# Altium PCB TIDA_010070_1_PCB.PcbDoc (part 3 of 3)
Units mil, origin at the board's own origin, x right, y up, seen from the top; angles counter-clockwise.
Board outline 3224 x 3643 mil, 4 copper layers (Top Layer, Ground, Power, Bottom Layer), stack 90.4 mil thick; 156 components, 57 nets, 333 pads, 411 vias.
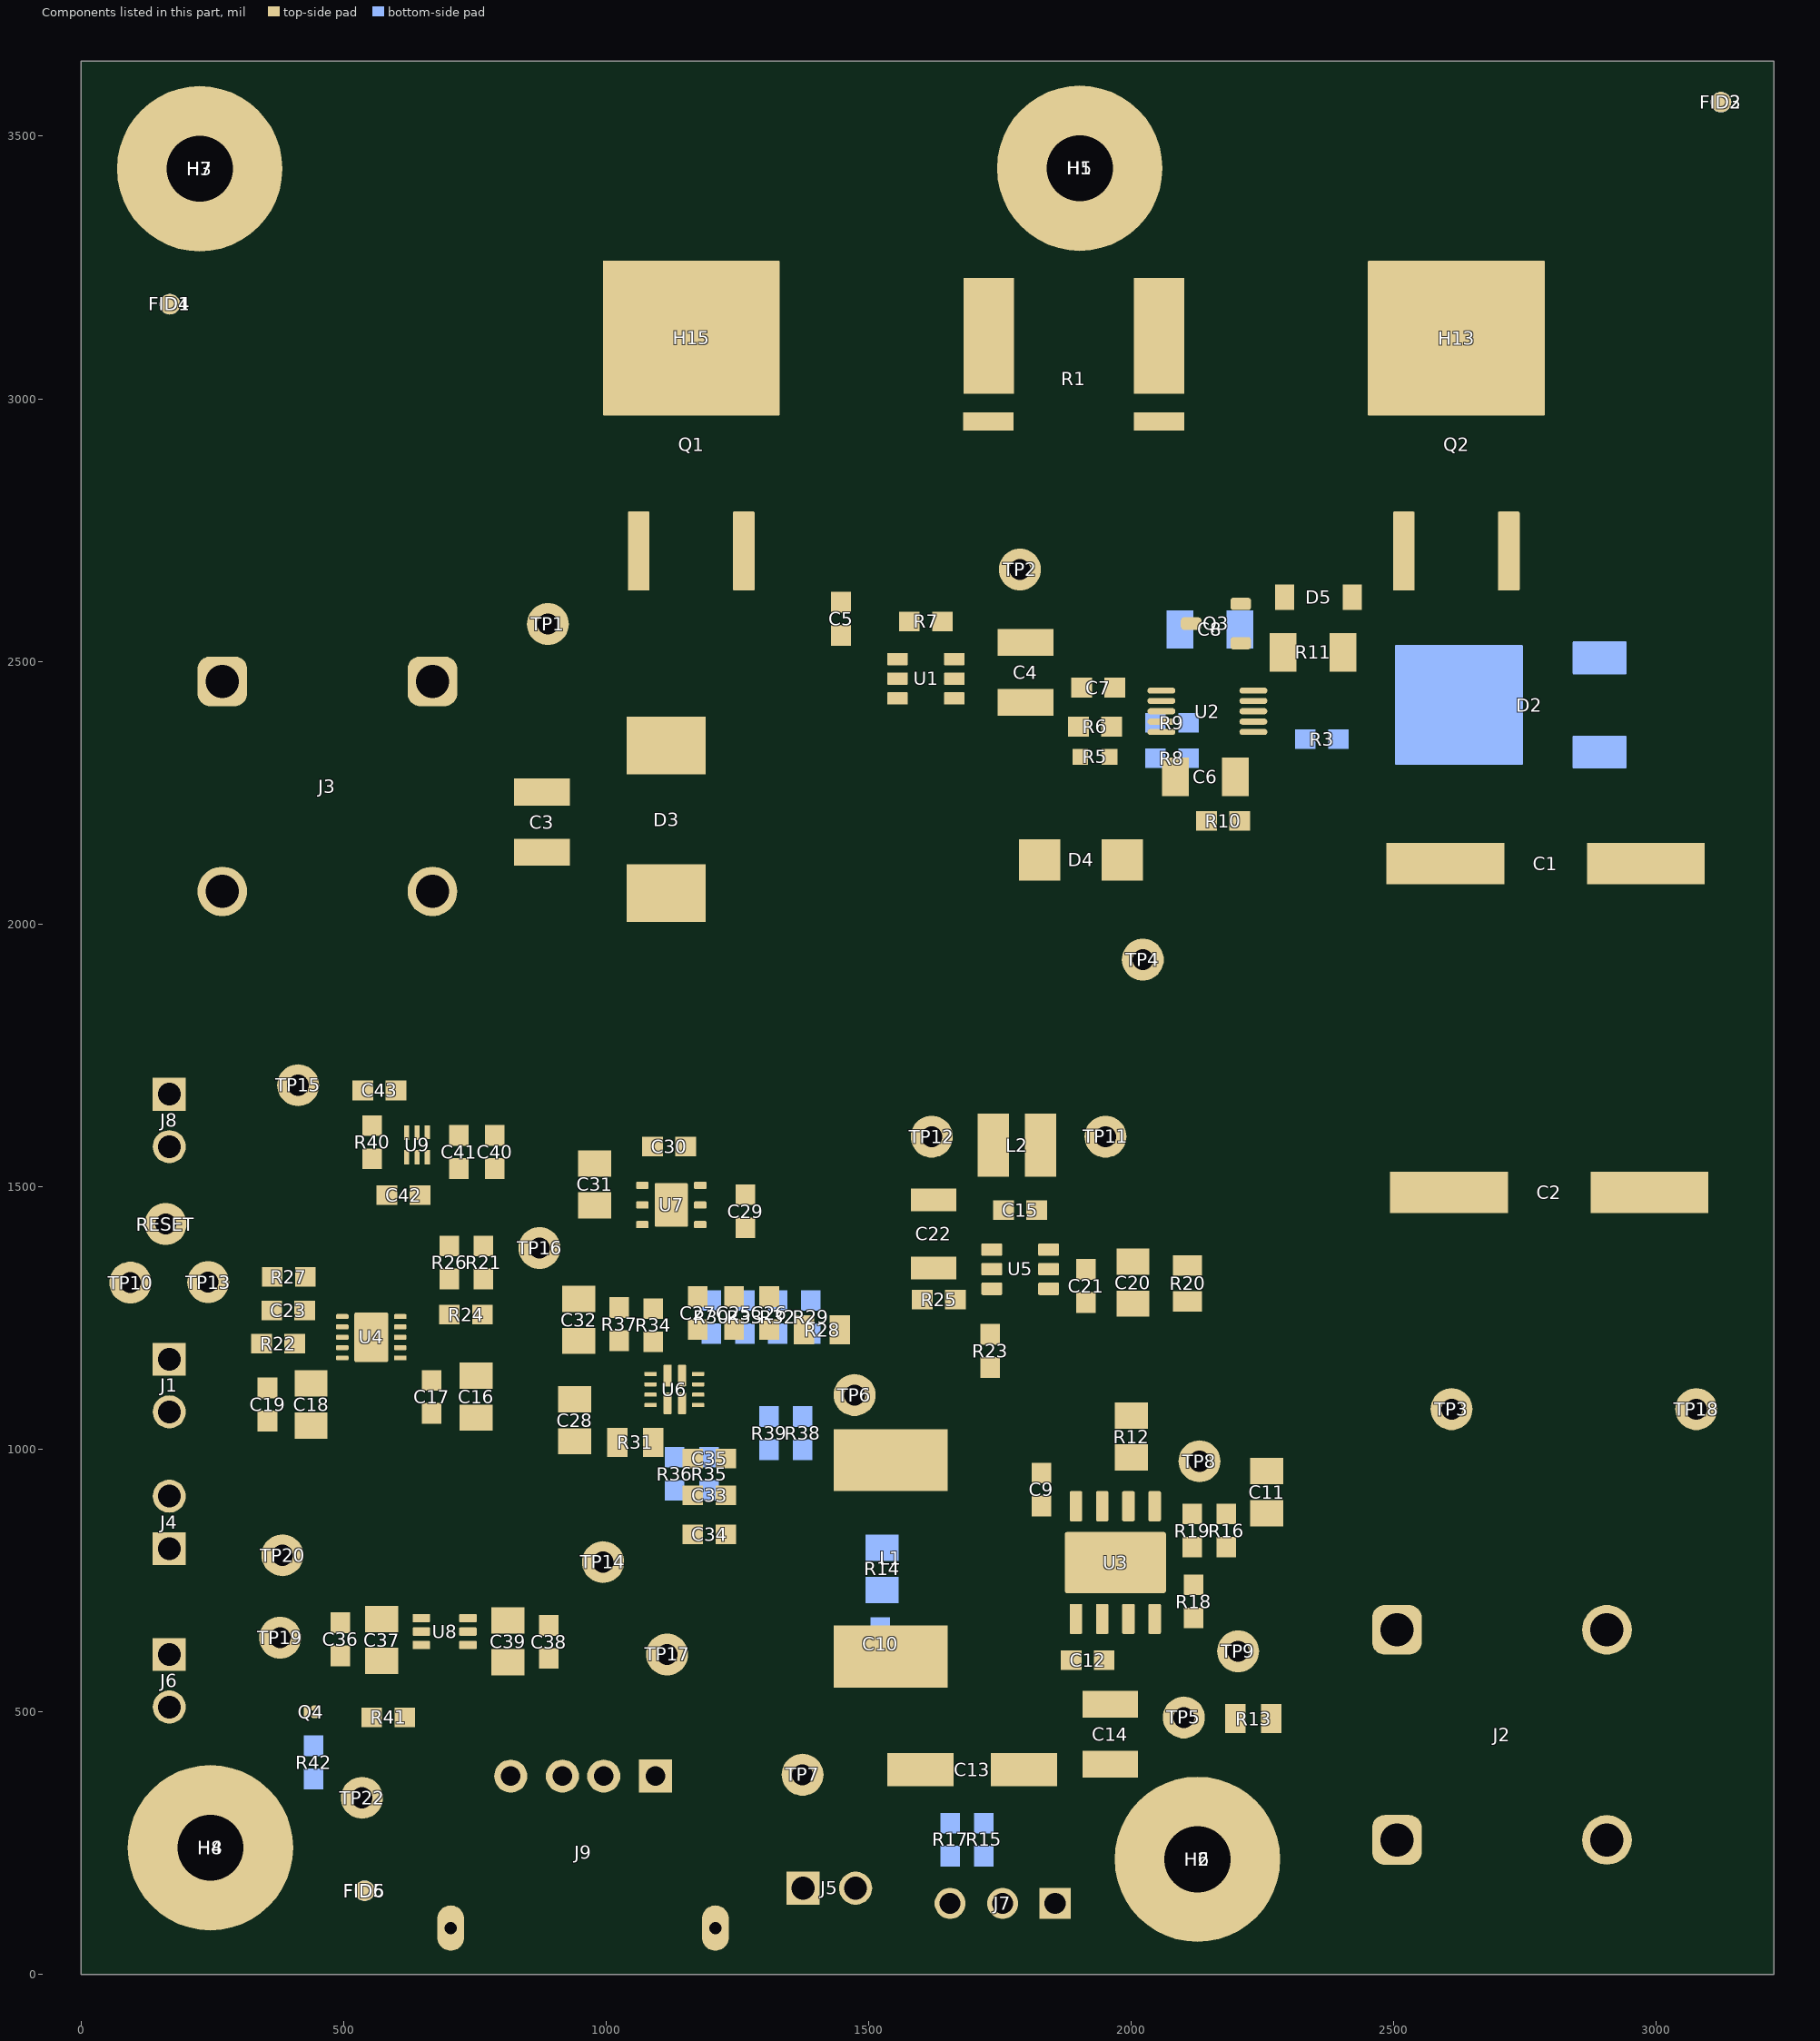
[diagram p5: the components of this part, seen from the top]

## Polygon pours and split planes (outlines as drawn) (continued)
NetC4_2 on Top Layer "Top Layer-No Net" (solid, remove dead copper, pour order 94): 1866,2496 1870,2500 1930,2500 1940,2510 1940,2741 1881,2800 1754,2800 1660,2894 1660,2990 1670,3000 1770,3000 1780,3010 1780,3229.15 1769.15,3240 1736.15,3240 1671,3305.15 1671,3582 1643,3610 419,3610 400,3591 400,3355.35 304.65,3260 304.65,3143.65 271,3110 60,3110 36.3,3086.3 36.3,2723.7 50,2710 470,2710 970,2710 980,2720 980,2807 989,2816 1437,2816 1442,2811 1442,2679 1451,2670 1595,2670 1621,2644 1621,2510 1635,2496 1697,2496
NetC5_1 on Top Layer "Top Layer-No Net" (solid, remove dead copper, pour order 92): 1594,2635.06 1583.06,2646 1409.02,2646 1404,2640.98 1404,2596 1409,2591 1529,2591 1539,2581 1539,2501 1549,2491 1573.92,2491 1573.92,2535.92 1589,2551 1594,2556
GND on Top Layer "Top Layer-No Net" (solid, remove dead copper, pour order 162): 623,1522 625,1524 633,1524 636,1527 644,1527 647,1524 680,1524 687,1531 687,1556 689,1558 807,1558 809,1556 809,1455 807,1453 625,1453 623,1455
Reset on Top Layer "Top Layer-No Net" (solid, remove dead copper, pour order 164): 565,1466 339,1466 258,1385 130,1385 120,1395 120,1461 130,1471 254,1471 352,1569 625,1569 625,1542 602,1519 602,1503
VCC_5V_MAINS on Top Layer "Top Layer-No Net" (solid, remove dead copper, pour order 166): 715.01,1178 761.11,1224.1 782.9,1224.1 790,1217 790,1116.36 784.64,1111 618,1111 600.49,1128.51 600.49,1178
VCC_ENC1 on Top Layer "Top Layer-No Net" (solid, remove dead copper, pour order 168): 50,1120 40,1130 40,1340 60,1360 119,1360 140,1339 140,1231 150,1221 334,1221 363.25,1221 367.54,1216.7 367.54,1168.51 374.71,1161 473.72,1161 486.35,1173.63 501.91,1173.63 504.26,1171.28 504.26,1105.26 490,1091 326,1091 297,1120
GND on Top Layer "Top Layer-GND 1" (solid, remove dead copper, pour order 170): 341,1068 466.08,1068 480.05,1054.04 480.05,1028.95 488,1021 634,1021 644,1031 644,1079 650,1085 784.18,1085 804,1065.18 804,931 794,921 363.82,921 354,930.82 354,1001 334,1021 334,1061
NetC23_2 on Top Layer "Top Layer-GND" (solid, remove dead copper, pour order 172): 512,1349 512,1271.91 522,1261.91 522,1087.05 506,1071.05 506,1050 509,1047 615,1047 619,1051 619,1074.15 587,1106.15 587,1243 591.06,1247.06 634.06,1247.06 644,1257 644,1351 654,1361 720,1361 724,1365 724,1421 714,1431 365,1431 335,1401 335,1318 335,1252 341,1246 389,1246 392,1249 392,1356 396,1360 501,1360
V_5VBAT on Top Layer "Top Layer-GND" (solid, remove dead copper, pour order 176): 50,710 661,710 664,707 664,701.33 664,671 615,671 606,662 606,652 605,651 460,651 440,631 440,570 430,560 260,560 50,560 40,570 40,700
VCC_ENC2 on Top Layer "Top Layer-GND" (solid, remove dead copper, pour order 178): 714,654.59 721,647.59 766.1,647.59 772.69,641 924,641 934,651 934,832.45 906.45,860 100,860 50,860 40,850 40,750 50,740 705,740 714,731
GND on Top Layer "Top Layer-GND" (solid, remove dead copper, pour order 180): 599.82,626 614,611.82 614,581.33 630.33,565 667,565 684,582 684,621 694,631 914,631 924,621 924,542 912,530 670,530 660,520 660,431 649,420 605,420 594,431 594,541 590,545 487,545 469.26,562.74 469.26,620.26 475,626
GND on Top Layer "Top Layer-GND" (solid, remove dead copper, pour order 192): 2820,50 2836,34 3183,34 3189.7,40.7 3189.7,2620.3 3159.85,2650.15 2830.15,2650.15 2820,2640
VCC_48V on Top Layer "Top Layer-GND" (solid, remove dead copper, pour order 198): 2620,2770 2630,2780 2764,2780 2774,2770 2774,50 2759.3,35.3 2344.7,35.3 2330,50 2330,406 2306,430 2251,430 2240,441 2240,528 2252,540 2295.75,540 2330,574.25 2330,1121 2330,2207 2470,2347 2470,2396 2456,2410 2432,2410 2426,2416 2426,2432.51 2433.49,2440 2457,2440 2470,2453 2470,2560 2480,2570 2578,2570 2620,2612
GND on Bottom Layer "Top Layer-GND" (solid, remove dead copper, pour order 274): 2120.69,2171.31 2082,2210 2082,2303 2092,2313 2092,2502 2052,2542 2052,2638 2064,2650 2291,2650 3160,2650 3189.89,2620.11 3190,2614 3190,80 3140,30 80,30 40.12,69.88 40.12,2131.12 80,2171 1289.17,2171 1350.17,2110 1850,2110 1900,2060 1900,1863.95 1919.95,1844 2101,1844 2120.69,1863.69
VCC_5V_MAINS on Bottom Layer "Top Layer-GND" (solid, remove dead copper, pour order 200): 1649,1389.8 1649.2,1389.8 1660,1379 1675,1379 1690,1394 1690,1400 1690,1661 1680.15,1670.85 1400.46,1670.85 1390,1660.39 1390,1400 1400.2,1389.8 1479.82,1389.8 1529.74,1389.8
VCC_5V_USB on Bottom Layer "Top Layer-GND" (solid, remove dead copper, pour order 210): 1050,680 1171,680 1180,671 1180,340 1170,330 1049.2,330 1040,339.2 1040,670
VCC_48V on Bottom Layer "Top Layer-GND" (solid, remove dead copper, pour order 242): 2330,50 2344.7,35.3 2759.3,35.3 2770,46 2770,2760 2750,2780 2630,2780 2620,2770 2620,2612 2598,2590 2380,2590 2367,2577 2367,2244 2330,2207 2330,1119
NetC9_1 on Bottom Layer "Top Layer-GND" (solid, remove dead copper, pour order 244): 1470,800 1480,790 1570,790 1580,800 1580,830 1590,840 1720,840 1730,850 1730,910 1720,920 1480,920 1470,910
VCC_15V on Bottom Layer "Top Layer-GND" (solid, remove dead copper, pour order 246): 1559.88,539.12 1570,529 1570,507 1560,497 1560,339.12 1549.88,329 1310.94,329 1299.94,340 1299.94,569.7 1310,579.75 1480.26,579.75 1488.26,588.26 1490,590 1490,610 1500,620 1549.88,620 1559.88,610
NetC4_2 on Bottom Layer "Top Layer-No Net" (solid, remove dead copper, pour order 256): 304.65,3260 304.65,3143.65 271,3110 60,3110 36.3,3086.3 36.3,2723.7 50,2710 470,2710 970,2710 980,2720 980,2810 990,2820 1359,2820 1440,2739 1509,2670 1620,2559 1683,2496 1699,2480 1868.16,2480 1894,2480 1901,2473 1920,2473 1927,2480 1941,2494 1941,2740 1780,2901 1780,3196.15 1736.15,3240 1671,3305.15 1671,3582 1643,3610 419,3610 400,3591 400,3355.35
NetH13_1 on Bottom Layer "Top Layer-No Net" (solid, remove dead copper, pour order 262): 3027,3619.7 3050,3596.7 3050,3500 3060,3490 3187.33,3490 3195,3482.33 3194.7,3446 3194.7,2695.7 3179,2680 2815,2680 2804,2691 2804,2791 2789,2806 2434,2806 2419,2791 2419,2701 2398,2680 2125,2680 2113.98,2691.02 2113.98,2876.02 1980.81,3009.19 1980.81,3329.81 2061,3410 2061,3570 2110.7,3619.7
NetC5_2 on Bottom Layer "Top Layer-GND" (solid, remove dead copper, pour order 266): 2120.69,2144.31 1995,2270 1942.6,2270 1935,2262.4 1935,2252 1927,2244 1890.27,2244 1880,2254.27 1880,2380 1870,2390 1631,2390 1530,2491 1431,2590 1350,2590 1340,2580 1340,2162.44 1361.44,2141 1867.41,2141 1916,2092.03 1916,1883.91 1929.94,1869.98 2097.98,1869.98 2120.69,1892.69
GND on Ground "Top Layer-GND" (solid, remove dead copper, pour order 268): 1295.95,2171 80,2171 40.12,2131.12 40.12,69.88 70,40 3150,40 3190,80 3190,2614 3189.89,2620.11 3160,2650 2280.16,2650 2250,2620.14 2250,2080 2240,2070 2160,2070 2150,2060 2150,2000 2140,1990 1910,1990 1900,2000 1900,2060 1850,2110 1356.95,2110
NetC5_2 on Ground "Top Layer-No Net" (solid, remove dead copper, pour order 122): 2150,2070 2160,2080 2160.69,2080 2233,2080 2244,2091 2244,2561 2235,2570 1980.09,2570 1970,2559.77 1970,2460 1960,2450 1601,2450 1590.18,2460.82 1590.18,2554.82 1575,2570 1370,2570 1360,2560 1360,2150 1370,2140 1871,2140 1916.05,2094.95 1916.05,1883.95 1930.02,1869.98 2129.44,1869.98 2150,1890.54
NetC23_2 on Ground "Top Layer-GND" (solid, remove dead copper, pour order 174): 334,1431 714,1431 724,1421 724,1051 714,1041 333.8,1041 324,1050.8 324,1421
NetC4_2 on Ground "Top Layer-No Net" (solid, remove dead copper, pour order 250): 1780,3010 1780,2901 1941,2740 1941,2494 1927,2480 1868.16,2480 1699,2480 1630,2480 1620,2490 1620,2645 1595,2670 1449,2670 1440,2679 1440,2806 1430,2816 989,2816 980,2807 980,2720 970,2710 470,2710 50,2710 36.3,2723.7 36.3,3246.3 50,3260 304.65,3260 400,3355.35 400,3591 419,3610 1643,3610 1671,3582 1671,3305.15 1736.15,3240 1780,3196.15
NetH13_1 on Ground "Top Layer-No Net" (solid, remove dead copper, pour order 258): 1980.81,3009.44 1990,3000.25 2114.02,2876.22 2114,2691 2125,2680 2410,2680 2420,2690 2420,2792 2434,2806 2789,2806 2804,2791 2804,2691 2815,2680 3179,2680 3189.7,2690.7 3189.7,3601.71 3183.71,3607.7 2098.7,3607.7 2061,3570 2061,3403 1980.81,3322.81
VCC_5V_MAINS on Power "Top Layer-GND" (solid, remove dead copper, pour order 196): 810,1050 820,1060 820,1560 830,1570 1370,1570 1400,1540 1400,1450 1410,1440 1730,1440 1740,1450 1740,1898 1730,1908 501,1908 490,1897 490,1060 500,1050
NetC3_2 on Power "Top Layer-No Net" (solid, remove dead copper, pour order 182): 1329.99,2790 1340,2779.99 1340,2387 1357,2370 1613,2370 1640,2397 1640,2441 1680,2441 1680,2230 1670,2220 140,2220 130,2230 130,2667 144,2681 894.05,2681 1192.56,2681 1220,2708.44 1220,2780 1230,2790
VCC_48V on Power "Top Layer-No Net" (solid, remove dead copper, pour order 188): 3180,30 3190,40 3190,2640 3180,2650 2790,2650 2780,2660 2780,2770 2770,2780 2630,2780 2620,2770 2620,2669 2581,2630 2270,2630 2260,2620 2260,2190 2260,1204 2350,1114 2350,50 2370,30
VCC_15V on Power "Top Layer-GND" (solid, remove dead copper, pour order 202): 1190,790 1200,800 1400,800 1410,810 1410,880 1410,1369.64 1420.36,1380 2190,1380 2200,1370 2200,420 2190,410 1940,410 1930,400 1930,70 1920,60 1200,60 1190,70
NetC28_2 on Power "Top Layer-GND" (solid, remove dead copper, pour order 204): 830,1020 840,1030 910,1030 920,1040 920,1480 930,1490 1340,1490 1350,1480 1350,880 1340,870 839.76,870 830,879.75
NetC4_2 on Power "Top Layer-No Net" (solid, remove dead copper, pour order 254): 1780,2880 1941,2719 1941,2494 1927,2480 1868.16,2480 1699,2480 1450,2480 1440,2490 1440,2810 1434,2816 989,2816 980,2807 980,2720 970,2710 470,2710 50,2710 36.3,2723.7 36.3,3246.3 50,3260 304.65,3260 400,3355.35 400,3591 419,3610 1643,3610 1671,3582 1671,3305.15 1736.15,3240 1780,3196.15
NetH13_1 on Power "Top Layer-No Net" (solid, remove dead copper, pour order 260): 1979.97,2700.02 2000,2680 2397.96,2680 2419,2701.04 2419,2791 2434,2806 2789,2806 2805,2790 2805,2690 2815,2680 3179,2680 3189.7,2690.7 3189.7,3601.71 3183.71,3607.7 2098.7,3607.7 2061,3570 2061,3403 1980,3322

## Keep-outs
Keep-Out Layer:
  lines w10: 1,0 1,3643 3225,3643 3225,0 1,0
  text ".Layer_Name" at 611,-2376.19 h60

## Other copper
Top Layer:
  rectangle net GND: 1770,1290 1810,1360
  text ".Layer_Name" at 611,-2376.19 h60
Ground:
  pour cut-out: 2139.98,1239 2139.98,1214 2123,1214 2123,1239
  text "GROUND" at 611,-2376.19 h60
Power:
  pour cut-out: 2976,264 2976,249 2965.81,249 2965.81,264
  text "POWER" at 627,-2377 h60
Bottom Layer:
  pour cut-out: 1125,857.39 1135.08,857.39 1135.47,857 1135.47,846 1125.04,846 1125,846.04
  text ".Layer_Name" at 611,-2376.19 h60

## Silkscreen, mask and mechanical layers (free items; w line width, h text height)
Top Overlay:
  lines w6: 56.99,1862 56.99,1849.01 47.74,1849.01 47.74,1836.02 83.96,1836.02 83.96,1849.01 74.71,1849.01 74.71,1862 ; 301.86,1007.02 323,985.88 323,982 323,958 323,925 334,914 427,914 ; 313,1238 313,1354 351,1392 351,1433 ; 397,1510 450,1510 467,1493 467,1435 467,1231.51 455.49,1220 445,1209.51 445,1180 ; 480.02,1284 480.02,1300 496.52,1300 ; 550,1140 630,1140 630,1240 ; 556.2,1862 556.2,1849.01 546.95,1849.01 546.95,1836.02 583.17,1836.02 583.17,1849.01 573.92,1849.01 573.92,1862 ; 759.46,2459.74 820,2459.74 ; 760.53,2029.47 760.53,2090.01 ; 789.99,2429.2 789.99,2489.74 ; 1523.98,470 1553.98,470 ; 1538.98,455 1538.98,485 ; 1965,2222 1980,2237 1980,2284 ; 2160.28,768 2200,768 2213.25,754.75 2222.45,754.75 ; 2226,830 2288,830 2295,823 ; 2478.47,768.27 2539.01,768.27 ; 2509,737.73 2509,798.27 ; 2876.47,771.3 2937.01,771.3 ; 3106,43.99 3118.99,43.99 3118.99,34.74 3131.98,34.74 3131.98,70.96 3118.99,70.96 3118.99,62.01 3106.3,62.01 3106,61.71 ; 3106,543.2 3118.99,543.2 3118.99,533.95 3131.98,533.95 3131.98,570.17 3118.99,570.17 3118.99,560.92 3106,560.92 ; 427,914 420,921 420,907 427,914 ; 36.25,1862 731.99,1862 731.99,2662 36.25,2662 36.25,1862 ; 410,470 462,470 462,529 410,529 410,470 ; 2306,37.87 3106,37.87 3106,718.99 2306,718.99 2306,37.87
  text ".Layer_Name" at 611,-2376.19 h60
Bottom Overlay:
  lines w6: 2490,2280 2490,2562 2940,2562 2960,2562 2960,2280 2490,2280
  text ".Layer_Name" at 611,-2376.19 h60
Top Paste:
  text ".Layer_Name" at 611,-2376.19 h60
Bottom Paste:
  text ".Layer_Name" at 611,-2376.19 h60
Top Solder:
  region: 2250,2714 2243,2721 2243,3577 2258,3592 2993,3592 3007,3578 3007,2732 2989,2714 2835,2714 2835,2810 2830,2815 2408,2815 2399,2806 2399,2714
  region: 776,3571 1520,3571 1563,3528 1563,2726 1551,2714 1373.66,2714 1372.04,2715.62 1372.04,2815.62 951.62,2815.62 946,2810 946,2725 936,2715 743,2715 736,2722 736,3531
  text ".Layer_Name" at 611,-2376.19 h60
  text ".Layer_Name" at 611,-2376.19 h60
Bottom Solder:
  text ".Layer_Name" at 611,-2376.19 h60
Drill Guide:
  text ".Layer_Name" at 611,-2376.19 h60
M1 Board Outline:
  the board outline again, w10
M2 Board Dimensions:
  rectangle: 159,-1917.7 534,-1792.7
  rectangle: 34,-1792.7 159,-1667.7
  lines w7: 34,-1792.7 1034,-1792.7 ; 159,-1917.7 159,-1667.7 ; 284,-1917.7 284,-1667.7 ; 534,-1917.7 534,-1667.7 ; 784,-1917.7 784,-1667.7 ; 34,-1917.7 34,-1667.7 1034,-1667.7 1034,-1917.7 34,-1917.7
  lines w10: 1,0 1,3643 3225,3643 3225,0 1,0
M3 3D STEP Top:
  text ".Layer_Name" at 611,-2376.19 h60
M4 3D STEP Bottom:
  text ".Layer_Name" at 611,-2376.19 h60
M5 Assembly Top:
  circle w10: c1179.12,1427.51 r9.9
  lines w6: 1535,495 1565,495 ; 1550,480 1550,510 ; 1050,1400 1050.46,1399.54 1208.54,1399.54 1210,1401 1210,1520 1051,1520 1050,1519 1050,1400
  lines w10: -258,-2447.87 6342,-2447.87 ; -258,-2244.53 6344,-2244.53 ; -258,-2041.2 -258,-2651.2 3747,-2651.2 6344,-2651.2 6344,-2041.2 -257.5,-2041.2 -257.5,-2651.2 1318,-2651.2 ; 2207,-2651.2 2207,-2041.2 ; 3474,-2244.53 3474,-2041.2 ; 4314,-2244.53 4314,-2041.2 ; 4936,-2657.7 4936,-2454.87
  text "COMPONENTS MARKED 'DNP' SHOULD NOT BE POPULATED." at 1187.5,-1836.2 h60
  text "ASSEMBLY VARIANT:" at 1187,-1951.7 h60
  text ".VariantName" at 2223,-1951.7 h60
  text "PCB VIEWED FROM TOP SIDE" at -194.5,-2173.37 h60
  text "BOARD #:" at 2282,-2173.37 h60
  text ".PRJ_Number" at 2827.5,-2173.37 h60
  text "REV:" at 3672,-2173.37 h60
  text ".PCB_Rev" at 3963.5,-2173.37 h60
  text "SVN REV:" at 4510,-2173.37 h60
  text ".VersionControl_RevNumber" at 5016,-2173.37 h60
  text "TID #:" at 2282,-2376.7 h60
  text ".TID" at 2827.5,-2376.7 h60
  text "M5 Assembly Top" at 643,-2380 h60
  text "PLOT NAME =" at -194.5,-2582.04 h60
  text ".plot_File_Name" at 611,-2582.04 h60
  text "GENERATED    :" at 2284,-2582.04 h60
  text ".Print_Date" at 3153.5,-2582.04 h60
  text ".Print_Time" at 3882.5,-2582.04 h60
  text "TEXAS INSTRUMENTS" at 5147,-2582.04 h60
M6 Assembly Bottom:
  lines w10: -258.5,-2245.03 6343.5,-2245.03 ; -256.5,-2448.37 6343.5,-2448.37 ; 1149.5,-2658.2 1149.5,-2455.37 ; 1771.5,-2245.03 1771.5,-2041.7 ; 2611.5,-2245.03 2611.5,-2041.7 ; 3878.5,-2651.7 3878.5,-2041.7 ; 4767.5,-2651.7 6343,-2651.7 6343,-2041.7 -258.5,-2041.7 -258.5,-2651.7 2338.5,-2651.7 6343.5,-2651.7 6343.5,-2041.7
  text "COMPONENTS MARKED 'DNP' SHOULD NOT BE POPULATED." at 6136,-1835.7 h60
  text ".VariantName" at 5092,-1951.7 h60
  text "ASSEMBLY VARIANT:" at 6131,-1951.7 h60
  text ".VersionControl_RevNumber" at 1069.5,-2173.87 h60
  text "SVN REV:" at 1575.5,-2173.87 h60
  text ".PCB_Rev" at 2122,-2173.87 h60
  text "REV:" at 2413.5,-2173.87 h60
  text ".PRJ_Number" at 3258,-2173.87 h60
  text "BOARD #:" at 3803.5,-2173.87 h60
  text "PCB VIEWED FROM BOTTOM SIDE" at 6280,-2173.87 h60
  text ".TID" at 3258,-2377.2 h60
  text "TID #:" at 3803.5,-2377.2 h60
  text "M6 Assembly Bottom" at 5012,-2383 h60
  text "TEXAS INSTRUMENTS" at 938.5,-2582.54 h60
  text ".Print_Time" at 2203,-2582.54 h60
  text ".Print_Date" at 2932,-2582.54 h60
  text "GENERATED    :" at 3801.5,-2582.54 h60
  text ".plot_File_Name" at 5474.5,-2582.54 h60
  text "PLOT NAME =" at 6280,-2582.54 h60
M9 Title Sheet:
  drawing of 57 lines, arcs and shapes, not listed
  text "1" at 773.84,6518.8 h70
  text "2" at 3269.5,6518.8 h70
  text "3" at 5758.84,6518.8 h70
  text "4" at 8265.51,6518.8 h70
  text "5" at 10764.5,6518.8 h70
  text "6" at 13269.5,6518.8 h70
  text "A" at -382.5,5375.8 h70
  text "A" at 14417.5,5375.8 h70
  text "B" at -382.5,2995.8 h70
  text "B" at 14417.5,2995.8 h70
  text "C" at -382.5,620.8 h70
  text "C" at 14417.5,620.8 h70
  text "PROJECT TITLE:" at 11377.5,-1240.2 h45
  text ".PRJ_Title" at 11427.5,-1373.53 h70
  text "DESIGNED FOR:" at 11377.5,-1541.2 h45
  text ".PRJ_Customer" at 11427.5,-1681.2 h70
  text "D" at -382.5,-1749.2 h70
  text "D" at 14417.5,-1749.2 h70
  text "FILE NAME:" at 11377.5,-1841.2 h45
  text ".PCB_File_Name_No_Path" at 11427.5,-1961.2 h70
  text "Texas Instruments (TI) and/or its licensors do not warrant the accuracy or completeness of this specification" at 6408,-2123.04 h45
  text "ENGINEER:" at 11377.5,-2131.2 h45
  text "LAYOUT BY:" at 12882.5,-2131.2 h45
  text "or any information contained therein. TI and/or its licensors do not warrant that this design will meet" at 6363.01,-2235.7 h45
  text ".PRJ_Engineer" at 11427.5,-2286.19 h70
  text ".PCB_Layout" at 12933,-2286.19 h70
  text "the specifications, will be suitable for your application or fit for any particular purpose, or will operate in" at 6363.01,-2348.37 h45
  text "ALTIUM DESIGNER VERSION:" at 12882.5,-2441.2 h45
  text "an implementation. TI and/or its licensors do not warrant that the design is production worthy. You should" at 6363.01,-2461.04 h45
  text "completely validate and test your design implementation to confirm the system functionality for your application." at 6408,-2573.7 h45
  text ".print_Scale" at 11427.5,-2574.53 h70
  text ".Application_BuildNumber" at 12933,-2574.53 h70
  text "1" at 773.84,-2781.2 h70
  text "2" at 3269.5,-2781.2 h70
  text "3" at 5758.84,-2781.2 h70
  text "4" at 8265.51,-2781.2 h70
  text "5" at 10764.5,-2781.2 h70
  text "6" at 13269.5,-2781.2 h70
M10 Fab Notes:
  drawing of 189 lines, arcs and shapes, not listed
  text "THIS IS NOT AN IMPEDANCE CONTROL BOARD." at 11345,5065 h60
  text "ALL VIAS ARE TENTED EXCEPT THERMAL VIAS." at 11345,4971 h60
  text "DESIGN INFORMATION" at 12416.02,4838.47 h60
  text "MIN. TRACK WIDTH:" at 11771.46,4706.35 h60
  text "7.874" at 12770,4702 h60
  text "MIL" at 13070,4699 h60
  text "MIN. CLEARANCE:" at 11771.46,4582.22 h60
  text "0.2" at 12807.7,4582.22 h60
  text "mm" at 13022.46,4582.22 h60
  text "MIN. VIA PAD SIZE:" at 11771.46,4458.1 h60
  text "24" at 12837.71,4458.1 h60
  text "MIL" at 13022.46,4458.1 h60
  text "0.05mm (2MIL)" at 12466.46,4328.2 h60
  text "MINIMUM ANNULAR RING" at 11442.23,4319.97 h60
  text "EXTERNAL" at 13174.46,4319.97 h60
  text "PER" at 11642.23,4209.85 h60
  text "IPC-D-275 CLASS 2 LEVEL C" at 11862.23,4209.84 h60
  text "MIL, HOLES" at 13350.46,4109.37 h60
  text "+/-" at 12958,4100.78 h60
  text "+/-" at 13812,4100.78 h60
  text "REGISTRATION TOLERANCES:" at 11442.23,4099.72 h60
  text "METAL" at 12642,4099.72 h60
  text "5" at 13218.2,4099.72 h60
  text "3" at 14051.2,4099.72 h60
  text "MIL" at 14167.46,4099.72 h60
  text "HOLE SIZE TOLERANCE (UNLESS OTHERWISE SPECIFIED):" at 11442.23,4001.4 h60
  text "+/-" at 13812,3998.53 h60
  text "3" at 14051.2,3997.47 h60
  text "MIL" at 14167.46,3997.47 h60
  text "MATERIAL:" at 11367.46,3859.82 h60
  text "FR-4 High Tg" at 12353.9,3731.29 h60
  text "X" at 12209.46,3723.31 h60
  text "FR-408" at 11788.46,3718.79 h60
  text "OTHER" at 13276.46,3718.79 h60
  text "62 MIL (1.6mm) +/-10%" at 12108.56,3575.76 h60
  text "X" at 11988.46,3573.31 h60
  text "THICKNESS:" at 11442.23,3567.54 h60
  text "OTHER" at 13393.46,3567.54 h60
  text "TOLERANCE:" at 11442.23,3429.22 h60
  text "X" at 12290.46,3429.22 h60
  text "ANSI IPC-6012 TYPE 3 CLASS 2" at 12468.48,3429.22 h60
  text "OTHER +/-" at 12468.46,3285.03 h60
  text "BOW & TWIST:" at 11442.23,3139.84 h60
  text "X" at 12290.46,3139.84 h60
  text "ANSI IPC-6012 TYPE 3 CLASS 2" at 12468.48,3139.84 h60
  text "FAB NOTE:" at 5632,3100 h70
  text "OTHER +/-" at 12468.46,2993.15 h60
  text "PLEASE MAINTAIN 1oz COPPER THICKNESS FOR ALL 4 LAYER." at 5623,2979 h70
  text "DRILLING:" at 11367.46,2862.53 h60
  text "PLEASE MAINTAIN THE BOARD THICKNESS AS 1.6MM." at 5623,2855 h70
  text "NC_DRILL FILES" at 13128.46,2757.34 h60
  text "REFERENCE:" at 11442.23,2753.4 h60
  text "X" at 12099.46,2753.31 h60
  text "AS SHOWN" at 12277.46,2753.4 h60
  text "X" at 13000.46,2753.4 h60
  text "OTHER" at 13426.46,2611.15 h60
  text "PTH COPPER THICKNESS:" at 11441.91,2607.62 h60
  text "X" at 12581.14,2607.62 h60
  text "20-30 um" at 12709.14,2607.62 h60
  text "BOARD FINISH:" at 11367.46,2460.02 h60
  text "SILKSCREEN:" at 11522.68,2349.9 h60
  text "X" at 12480.46,2349.9 h60
  text "TOP" at 12597.46,2349.9 h60
  text "X" at 12990.46,2349.9 h60
  text "BOTTOM" at 13108.46,2349.9 h60
  text "SILKSCREEN COLOR:" at 11522.68,2194.71 h60
  text "X" at 12479.46,2194.71 h60
  text "WHITE" at 12597.46,2194.71 h60
  text "OTHER" at 13108.46,2194.71 h60
  text "X" at 12610.46,2051.26 h60
  text "GREEN" at 12728.46,2051.26 h60
  text "OTHER" at 13346.46,2051.26 h60
  text "SOLDER RESIST COLOR:" at 11522.68,2044.39 h60
  text "X" at 12610.46,1897.01 h60
  text "MATTE" at 12728.46,1897.01 h60
  text "SEMI-GLOSS" at 13346,1896.37 h60
  text "IMMERSION GOLD (ENIG)" at 12428.46,1724.24 h60
  text "ENEPIG" at 13766,1717.02 h60
  text "SURFACE FINISH:" at 11367.46,1716.02 h60
  text "X" at 12250.46,1716.02 h60
  text "IMM. TIN/SILVER OR EQUIV" at 11697,1578.7 h60
  text "OTHER" at 13128.46,1574.76 h60
  text "ARRAY/PANEL:" at 11367.46,1419.39 h60
  text "CUT AND TRIM PER M1 BOARD OUTLINE" at 12428.46,1411.16 h60
  text "N.C. ROUTE" at 12428.46,1275.2 h60
  text "X" at 13116.46,1275.2 h60
  text "V. SCORE" at 13294.46,1275.2 h60
  text "CERTIFICATION:" at 11367.46,1146.07 h60
  text "MATERIALS AND WORKMANSHIP FOR ALL PCBS" at 12092.46,1146.07 h60
  text "TO MEET OR EXCEED THE REQUIREMENTS OF:" at 12092.46,1052.01 h60
  text "X" at 11729.97,923.38 h60
  text "ANSI IPC-A-600F CLASS ->" at 11857.96,923.38 h60
  text "X" at 13505.97,923.38 h60
  text "2" at 13615.96,923.38 h60
  text "1" at 13300.96,921.88 h60
  text "3" at 13969.96,921.88 h60
  text "X" at 12541.97,775.69 h60
  text "RoHS" at 12669.96,775.69 h60
  text "OTHER" at 13314.36,775.69 h60
  text "PER ORDER" at 13711.42,775.69 h60
  text "ALL BOARDS MUST MEET OR EXCEED UL94-V0 REQUIREMENTS." at 11395,621.87 h60
  text "PCB MUST BEAR THE UL94V-0 UL REGISTERED MATERIAL ID NUMBER" at 11395,505.8 h60
  text "ADDITIONAL REQUIREMENTS:" at 11367.46,336.38 h60
  text "MICROSECTION:" at 11442.23,229.25 h60
  text "YES" at 12347.96,229.25 h60
  text "REQUIRED" at 13209.46,84.92 h60
  text "BARE BOARD ELEC. TEST:" at 11442.23,82.06 h60
  text "NONE" at 12747.96,82.06 h60
  text "X" at 13091.46,82.06 h60
  text "PER ORDER" at 13801.46,82.06 h60
  text "XX MIL VIAS REQUIRE NON-CONDUCTIVE FILL AND PLANARIZE" at 11610.38,-122.88 h59
  text "XX MIL VIAS REQUIRE CONDUCTIVE FILL AND PLANARIZE" at 11618.38,-226.86 h60
  text "OUTER XX MIL TRACES REQUIRE 50 OHM SINGLE-ENDED IMPEDANCE" at 11617.39,-390.24 h58
  text "LAYER 2 & 3 (INNER LAYERS) XX MIL WIDE, XX MIL SPACE / TRACES REQUIRE 100 OHM DIFFERENTIAL IMPEDANCE" at 11609.39,-625.96 h60
M11 Gerber Information:
  lines w10: -258,-2447.87 6342,-2447.87 ; -258,-2244.53 6344,-2244.53 ; -258,-2041.2 -258,-2651.2 3747,-2651.2 6344,-2651.2 6344,-2041.2 -257.5,-2041.2 -257.5,-2651.2 1318,-2651.2 ; 2207,-2651.2 2207,-2041.2 ; 3474,-2244.53 3474,-2041.2 ; 4314,-2244.53 4314,-2041.2 ; 4936,-2657.7 4936,-2454.87
  text "ALL ARTWORK VIEWED FROM TOP SIDE" at -194.5,-2173.37 h60
  text "BOARD #:" at 2282,-2173.37 h60
  text ".PRJ_Number" at 2827.5,-2173.37 h60
  text "REV:" at 3672,-2173.37 h60
  text ".PCB_Rev" at 3963.5,-2173.37 h60
  text "SVN REV:" at 4510,-2173.37 h60
  text ".VersionControl_RevNumber" at 5016,-2173.37 h60
  text "LAYER NAME =" at -194.5,-2376.19 h60
  text "TID #:" at 2282,-2376.7 h60
  text ".TID" at 2827.5,-2376.7 h60
  text "PLOT NAME =" at -194.5,-2582.04 h60
  text ".plot_File_Name" at 611,-2582.04 h60
  text "GENERATED    :" at 2284,-2582.04 h60
  text ".Print_Date" at 3153.5,-2582.04 h60
  text ".Print_Time" at 3882.5,-2582.04 h60
  text "TEXAS INSTRUMENTS" at 5147,-2582.04 h60
M13 Component Bodies Top:
  text ".Layer_Name" at 611,-2376.19 h60
M14 Component Bodies Bottom:
  text ".Layer_Name" at 611,-2376.19 h60
M15 Courtyards Top:
  text ".Layer_Name" at 611,-2376.19 h60
M16 Courtyards Bottom:
  text ".Layer_Name" at 611,-2376.19 h60
Drill Drawing:
  circle w10: c4535.62,1800.28 r20
  circle w10: c4535.62,1800.28 r33.33
  circle w10: c4535.62,900.28 r33.33
  lines w10: 4502.29,1033.61 4518.96,1033.61 4518.96,1016.94 4552.29,1016.94 4552.29,1033.61 4568.96,1033.61 4568.96,1066.94 4552.29,1066.94 4552.29,1083.61 4518.96,1083.61 4518.96,1066.94 4502.29,1066.94 4502.29,1033.61 ; 4502.29,1233.61 4568.96,1233.61 4535.62,1166.94 4502.29,1233.61 ; 4502.29,1316.94 4568.96,1316.94 4568.96,1383.61 4502.29,1383.61 4502.29,1316.94 ; 4502.29,1500.28 4535.62,1466.94 4568.96,1500.28 4535.62,1533.61 4502.29,1500.28 ; 4502.29,1616.94 4502.29,1633.61 4518.96,1650.28 4502.29,1666.94 4502.29,1683.61 4518.96,1683.61 4535.62,1666.94 4552.29,1683.61 4568.96,1683.61 4568.96,1666.94 4552.29,1650.28 4568.96,1633.61 4568.96,1616.94 4552.29,1616.94 4535.62,1633.61 4518.96,1616.94 4502.29,1616.94 ; 4502.29,1933.61 4518.96,1933.61 4535.62,1916.94 4552.29,1933.61 4568.96,1933.61 4552.29,1950.28 4568.96,1966.94 4552.29,1966.94 4535.62,1983.61 4518.96,1966.94 4502.29,1966.94 4518.96,1950.28 4502.29,1933.61 ; 4502.29,2066.94 4568.96,2066.94 4568.96,2133.61 4502.29,2133.61 4502.29,2066.94 ; 4502.29,2216.94 4535.62,2233.61 4568.96,2216.94 4552.29,2250.28 4568.96,2283.61 4535.62,2266.94 4502.29,2283.61 4518.96,2250.28 4502.29,2216.94 ; 4515.62,2080.28 4555.62,2080.28 4555.62,2120.28 4515.62,2120.28 4515.62,2080.28
  lines w15: 4442.5,821.94 9527.11,821.94 ; 4442.5,2321.94 9527.11,2321.94 ; 4993.38,671.94 4993.38,2471.94 ; 5593.22,671.94 5593.22,2471.94 ; 6742.88,671.94 6742.88,2471.94 ; 7248.76,671.94 7248.76,2471.94 ; 7982.56,671.94 7982.56,2471.94 ; 4442.5,671.94 9527.11,671.94 9527.11,2471.94 4442.5,2471.94 4442.5,671.94
  text "DRILL TABLE:" at 4446,2523 h70
  text "Symbol" at 4532.5,2366.94 h72
  text "Count" at 5038.38,2366.94 h72
  text "Hole Size" at 5638.22,2366.94 h72
  text "Plated" at 6787.88,2366.94 h72
  text "Hole Type" at 7293.76,2366.94 h72
  text "Drill Layer Pair" at 8027.56,2366.94 h72
  text "16" at 5038.38,2216.94 h60
  text "7.87mil (0.200mm)" at 5638.22,2216.94 h60
  text "PTH" at 6787.88,2216.94 h60
  text "Round" at 7293.76,2216.94 h60
  text "Top Layer - Bottom Layer" at 8027.56,2216.94 h60
  text "8" at 5038.38,2066.94 h60
  text "8.00mil (0.203mm)" at 5638.22,2066.94 h60
  text "PTH" at 6787.88,2066.94 h60
  text "Round" at 7293.76,2066.94 h60
  text "Top Layer - Bottom Layer" at 8027.56,2066.94 h60
  text "385" at 5038.38,1916.94 h60
  text "12.00mil (0.305mm)" at 5638.22,1916.94 h60
  text "PTH" at 6787.88,1916.94 h60
  text "Round" at 7293.76,1916.94 h60
  text "Top Layer - Bottom Layer" at 8027.56,1916.94 h60
  text "2" at 5038.38,1766.94 h60
  text "16.00mil (0.406mm)" at 5638.22,1766.94 h60
  text "PTH" at 6787.88,1766.94 h60
  text "Round" at 7293.76,1766.94 h60
  text "Top Layer - Bottom Layer" at 8027.56,1766.94 h60
  text "2" at 5038.38,1616.94 h60
  text "23.62mil (0.600mm)" at 5638.22,1616.94 h60
  text "PTH" at 6787.88,1616.94 h60
  text "Slot" at 7293.76,1616.94 h60
  text "Top Layer - Bottom Layer" at 8027.56,1616.94 h60
  text "4" at 5038.38,1466.94 h60
  text "37.00mil (0.940mm)" at 5638.22,1466.94 h60
  text "PTH" at 6787.88,1466.94 h60
  text "Round" at 7293.76,1466.94 h60
  text "Top Layer - Bottom Layer" at 8027.56,1466.94 h60
  text "25" at 5038.38,1316.94 h60
  text "40.00mil (1.016mm)" at 5638.22,1316.94 h60
  text "PTH" at 6787.88,1316.94 h60
  text "Round" at 7293.76,1316.94 h60
  text "Top Layer - Bottom Layer" at 8027.56,1316.94 h60
  text "10" at 5038.38,1166.94 h60
  text "43.31mil (1.100mm)" at 5638.22,1166.94 h60
  text "PTH" at 6787.88,1166.94 h60
  text "Round" at 7293.76,1166.94 h60
  text "Top Layer - Bottom Layer" at 8027.56,1166.94 h60
  text "8" at 5038.38,1016.94 h60
  text "62.99mil (1.600mm)" at 5638.22,1016.94 h60
  text "PTH" at 6787.88,1016.94 h60
  text "Round" at 7293.76,1016.94 h60
  text "Top Layer - Bottom Layer" at 8027.56,1016.94 h60
  text "4" at 5038.38,866.94 h60
  text "125.98mil (3.200mm)" at 5638.22,866.94 h60
  text "PTH" at 6787.88,866.94 h60
  text "Round" at 7293.76,866.94 h60
  text "Top Layer - Bottom Layer" at 8027.56,866.94 h60
  text "464 Total" at 5038.38,716.94 h60
  text "Slot definitions :" at 4532.5,571.97 h60
  text "Routed Path Length" at 5565.19,571.97 h60
  text "= Calculated from tool start centre position to tool end centre position." at 6667.86,571.97 h60
  text "Hole Length" at 5565.19,471.99 h60
  text "= Routed Path Length + Tool Size = Slot length as defined in the PCB layout" at 6257.99,471.99 h60
  text "DRILL TOLERANCE:" at 4811,206 h60
  text "FOR 7.87MIL VIA +0/-7.87MIL" at 4583,82 h60
  text "FOR 8MIL VIA +0/-8MIL" at 4583,-27 h60
  text "FOR 12MIL VIA +0/-12MIL" at 4583,-130 h60
  text "FOR 16MIL VIA +0/-16MIL" at 4583,-236 h60
  text "FOR PTH  DRILLS +/-3 MIL" at 4583,-344 h60
  text ".Layer_Name" at 611,-2376.19 h60
M17 Embedded Cavity:
  text ".Layer_Name" at 611,-2376.19 h60
M18 Embedded Assembly:
  text ".Layer_Name" at 611,-2376.19 h60
M19 Embedded Keepout:
  text ".Layer_Name" at 611,-2376.19 h60

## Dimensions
34,-1917.7 to 1034,-1917.7 on M2 Board Dimensions
1,0 to 1,3643 on M2 Board Dimensions
1,3643 to 3225,3643 on M2 Board Dimensions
